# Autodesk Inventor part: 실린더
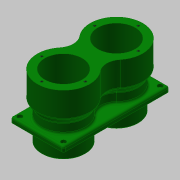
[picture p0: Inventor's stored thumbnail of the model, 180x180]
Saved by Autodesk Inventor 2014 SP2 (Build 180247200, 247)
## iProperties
Created: 2016-11
Part Number: 실린더
Material: 알루미늄 6061
Document SubType Name: Modeling
Designer: mduedu
Density: 2.71 g/cm^3
Mass: 1199.25 g
Surface Area: 1038.68 cm^2
Volume: 442.528 cm^3
Appearance: 진녹색
Author: mduedu
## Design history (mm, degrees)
sketch "스케치1"
  geometry: L1 (0, 0)-(0, 101); L2 (30, 0)-(30, 101); L3 (30, 101)-(42, 101); L4 (42, 101)-(42, 61); L5 (42, 61)-(35, 51); L6 (35, 51)-(35, 0); L7 (35, 0)-(30, 0)
  constraints: 14 end point, 4 parallel, 2 horizontal alignment, 1 perpendicular, 1 vertical
  dimensions: "d0" = 101 distance of L1.start L1.end; "d1" = 60 diameter of L2.end L1; "d2" = 84 diameter of L3.end L1; "d3" = 70 diameter of L6.end L1; "d4" = 40 distance of L3.end L4.end; "d5" = 50 vertical distance of L5.end L3.end
revolve "회전1" stored, may be unused: angle "d6" = 90 deg
node "작업 평면1"
sketch "스케치2"
  geometry: L1 (-42.5, -42.5)-(42.5, -42.5); L2 (42.5, -42.5)-(42.5, 42.5); L3 (42.5, 42.5)-(-42.5, 42.5); L4 (-42.5, 42.5)-(-42.5, -42.5); L5 (-42.5, -42.5)-(42.5, 42.5); L6 (42.5, -42.5)-(-42.5, 42.5); C1 r 35 at (0, 0) reference; C2 r 35 at (0, 0); 1 further point
  constraints: 12 end point, 2 midpoint, 2 parallel, 2 perpendicular, 1 centre point, 1 coincident, 1 concentric, 1 horizontal
  dimensions: "d8" = 85 distance of L2.end L3.end
extrude "돌출1" join sketch "스케치2" distance "d10" = 8; taper "d11" = 0 deg
chamfer "모따기1" distance "d14" = 1; stored, may be unused: second distance "d15" = 2, angle "d16" = 45 deg
chamfer "모따기2" distance "d17" = 5; stored, may be unused: second distance "d18" = 2, angle "d19" = 15 deg
sketch "스케치3"
  geometry: L1 (-35, -35)-(35, -35); L2 (35, -35)-(35, 35); L3 (35, 35)-(-35, 35); L4 (-35, 35)-(-35, -35); L5 (-35, -35)-(35, 35); L6 (35, -35)-(-35, 35); 3 further points
  constraints: 12 end point, 2 coincident, 2 midpoint, 2 parallel, 1 horizontal, 1 perpendicular
  dimensions: "d20" = 70 distance of L3.end L2.end; "d21" = 70 distance of L2.end L1.end
sketch "스케치4"
  geometry: 2 further points
  constraints: 2 other
hole "구멍1" sketch "스케치4" at (-35, 35), (35, 35) diameter "d22" = 4.5; stored, may be unused: countersink angle "d26" = 90 deg, drill point angle "d28" = 0 deg; dims "d23" = 6, "d24" = 8, "d25" = 4.6, "d27" = 8
sketch "스케치5"
  geometry: 3 further points
  constraints: 3 other
hole "구멍2" sketch "스케치5" at (35, 0), (-35, 0), (0, 35) diameter "d29" = 4.134; stored, may be unused: countersink angle "d33" = 90 deg, drill point angle "d35" = 120 deg; dims "d30" = 7.5, "d31" = 4, "d32" = 2, "d34" = 10
fillet "모깎기3" dims "d36" = 3
fillet "모깎기4" dims "d37" = 3
sketch "스케치6"
  geometry: L1 (0, 0)-(0, -85); A1 r 42 centre (0, 0) between (32.469, -26.642) and (-32.469, -26.642) reference; A2 r 42 centre (0, -85) between (32.469, -58.358) and (-32.469, -58.358) reference; A3 r 25 centre (51.795, -42.5) between (32.469, -58.358) and (32.469, -26.642); A4 r 25 centre (-51.795, -42.5) between (-32.469, -26.642) and (-32.469, -58.358); A5 r 25 centre (51.795, -42.5) between (32.469, -26.642) and (32.469, -58.358); A6 r 25 centre (-51.795, -42.5) between (-32.469, -58.358) and (-32.469, -26.642); A7 r 42 centre (0, 0) between (-32.469, -26.642) and (32.469, -26.642); A8 r 42 centre (0, -85) between (32.469, -58.358) and (-32.469, -58.358); A9 r 42 centre (0, 0) between (32.469, -26.642) and (-32.469, -26.642); A10 r 42 centre (0, -85) between (-32.469, -58.358) and (32.469, -58.358); 1 further point
  constraints: 20 point on circle, 8 centre point, 2 coincident, 2 end point, 2 tangent, 1 symmetric about line, 1 vertical, 1 other
  dimensions: "d38" = 50 diameter of A3
node "작업 평면2"
sketch "스케치7"
  geometry: A1 r 25 centre (9.795, -42.5) between (-9.531, -26.642) and (-9.531, -58.358) reference; A2 r 42 centre (-42, 0) between (-74.469, -26.642) and (-9.531, -26.642) reference; A3 r 42 centre (-42, -85) between (-9.531, -58.358) and (-74.469, -58.358) reference; A4 r 25 centre (-93.795, -42.5) between (-74.469, -58.358) and (-74.469, -26.642) reference; 1 further point
node "작업 평면3"
sketch "스케치8"
  geometry: L1 (-35, 0)-(-35, -85); A1 r 35 centre (-35, 0) between (-10.294, -24.792) and (-59.706, -24.792) reference; A2 r 35 centre (-35, -85) between (-10.294, -60.208) and (-59.706, -60.208) reference; A3 r 25 centre (7.353, -42.5) between (-10.294, -60.208) and (-10.294, -24.792); A4 r 25 centre (-77.353, -42.5) between (-59.706, -24.792) and (-59.706, -60.208); A5 r 25 centre (7.353, -42.5) between (-10.294, -24.792) and (-10.294, -60.208); A6 r 25 centre (-77.353, -42.5) between (-59.706, -60.208) and (-59.706, -24.792); A7 r 35 centre (-35, 0) between (-59.706, -24.792) and (-10.294, -24.792); A8 r 35 centre (-35, -85) between (-10.294, -60.208) and (-59.706, -60.208); 1 further point
  constraints: 16 point on circle, 6 centre point, 2 coincident, 2 end point, 2 tangent, 1 symmetric about line, 1 vertical, 1 other
  dimensions: "d40" = 50 diameter of A3
sketch "스케치9"
  geometry: A1 r 25 centre (42.353, -42.5) between (24.706, -24.792) and (24.706, -60.208) reference; A2 r 35 centre (0, 0) between (-24.706, -24.792) and (24.706, -24.792) reference; A3 r 35 centre (0, -85) between (24.706, -60.208) and (-24.706, -60.208) reference; A4 r 25 centre (-42.353, -42.5) between (-24.706, -60.208) and (-24.706, -24.792) reference; 1 further point
feature "로프트1" sketch "스케치8", "스케치9" dims "d42" = 0, "d43" = 90 deg, "d44" = 0, "d45" = 90 deg
feature "로프트2" dims "d46" = 0, "d47" = 90 deg, "d48" = 0, "d49" = 90 deg
  node "모서리1"
feature "로프트3" dims "d50" = 0, "d51" = 90 deg, "d52" = 0, "d53" = 90 deg
  node "모서리2"
fillet "모깎기5" dims "d54" = 3
node "솔리드1"
mirror "대칭1"
other parameters: "d7" = -27
